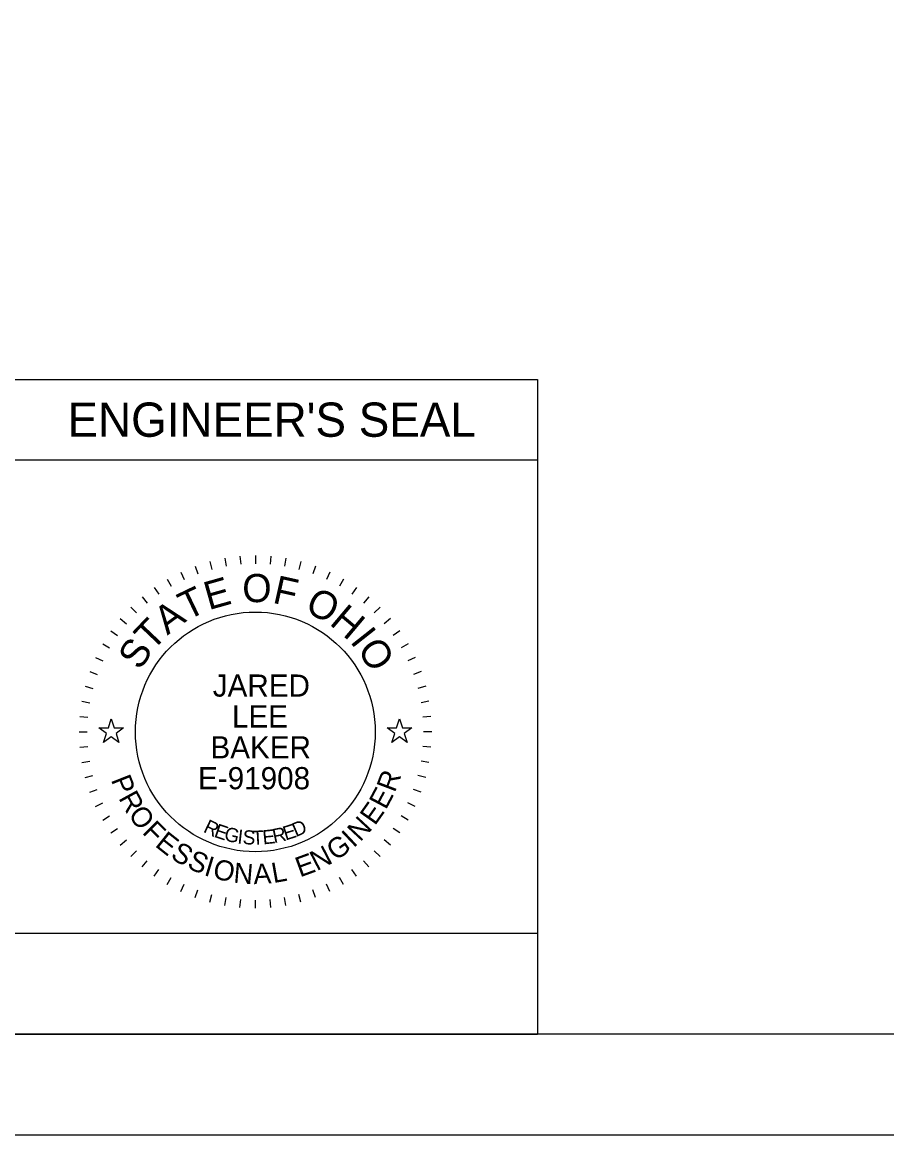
# Model space of a CAD drawing. Extents: x 0 to 70.2, y 0 to 31.4.
# Drawn here: x 21.1 to 25.39, y 0 to 5.52 of the extents above; entities that cross this region are included whole.
import ezdxf

# ---------------------------------------------------------------- set-up
doc = ezdxf.new("R2010")
doc.units = 0
for name, color, linetype in [('SH_Border', 7, 'Continuous'), ('SH_Cut_Line', 7, 'Continuous'), ('SH_Data', 7, 'Continuous'), ('SH_Seal', 7, 'Continuous')]:
    doc.layers.add(name, color=color, linetype=linetype)

msp = doc.modelspace()

# ---------------------------------------------------------------- linework, layer by layer
at = {"layer": 'SH_Border'}
msp.add_lwpolyline([(1.5, 21.5), (33.5, 21.5), (33.5, 0.5), (1.5, 0.5)], close=True, dxfattribs=at)
at = {"layer": 'SH_Cut_Line'}
msp.add_lwpolyline([(0, 0), (34, 0), (34, 22), (0, 22)], close=True, dxfattribs=at)
at = {"layer": 'SH_Data'}
for p, q in [((20.8533, 3.75), (23.6533, 3.75)), ((23.6533, 3.75), (23.6533, 0.5)), ((20.8533, 3.35), (23.6533, 3.35)), ((20.8533, 0.5), (23.6533, 0.5))]:
    msp.add_line(p, q, dxfattribs=at)
msp.add_lwpolyline([(20.8533, 0.5), (20.8533, 1), (23.6533, 1), (23.6533, 0.5)], close=True, dxfattribs=at)
at = {"layer": 'SH_Seal'}
for p, q in [((22.2533, 2.875), (22.2533, 2.835)), ((21.954, 2.8222), (21.9677, 2.7846)), ((22.0268, 2.8452), (22.0372, 2.8065)), ((22.1013, 2.8617), (22.1083, 2.8223)), ((22.177, 2.8717), (22.1805, 2.8318)), ((22.3295, 2.8717), (22.326, 2.8318)), ((22.4052, 2.8617), (22.3983, 2.8223)), ((22.4797, 2.8452), (22.4694, 2.8065)), ((22.5525, 2.8222), (22.5389, 2.7846)), ((21.8835, 2.793), (21.9004, 2.7568)), ((22.6231, 2.793), (22.6062, 2.7568)), ((21.7514, 2.7168), (21.7743, 2.684)), ((21.8158, 2.7578), (21.8358, 2.7231)), ((22.6908, 2.7578), (22.6708, 2.7231)), ((22.7552, 2.7168), (22.7322, 2.684)), ((21.6908, 2.6703), (21.7165, 2.6396)), ((22.8157, 2.6703), (22.79, 2.6396)), ((21.6346, 2.6187), (21.6628, 2.5904)), ((22.872, 2.6187), (22.8437, 2.5904)), ((21.583, 2.5624), (21.6136, 2.5367)), ((22.9236, 2.5624), (22.8929, 2.5367)), ((21.5365, 2.5019), (21.5693, 2.4789)), ((22.97, 2.5019), (22.9373, 2.4789)), ((21.4955, 2.4375), (21.5301, 2.4175)), ((23.011, 2.4375), (22.9764, 2.4175)), ((21.4603, 2.3698), (21.4965, 2.3529)), ((23.0463, 2.3698), (23.01, 2.3529)), ((21.431, 2.2993), (21.4686, 2.2856)), ((23.0755, 2.2993), (23.0379, 2.2856)), ((21.4081, 2.2265), (21.4467, 2.2161)), ((23.0985, 2.2265), (23.0598, 2.2161)), ((21.3916, 2.1519), (21.431, 2.145)), ((23.115, 2.1519), (23.0756, 2.145)), ((21.3816, 2.0763), (21.4214, 2.0728)), ((23.1249, 2.0763), (23.0851, 2.0728)), ((21.3783, 2), (21.4183, 2)), ((23.1283, 2), (23.0883, 2)), ((21.3816, 1.9237), (21.4214, 1.9272)), ((23.1249, 1.9237), (23.0851, 1.9272)), ((21.3916, 1.8481), (21.431, 1.855)), ((23.115, 1.8481), (23.0756, 1.855)), ((21.4081, 1.7735), (21.4467, 1.7839)), ((23.0985, 1.7735), (23.0598, 1.7839)), ((21.431, 1.7007), (21.4686, 1.7144)), ((23.0755, 1.7007), (23.0379, 1.7144)), ((21.4603, 1.6302), (21.4965, 1.6471)), ((23.0463, 1.6302), (23.01, 1.6471)), ((21.4955, 1.5625), (21.5301, 1.5825)), ((23.011, 1.5625), (22.9764, 1.5825)), ((21.5365, 1.4981), (21.5693, 1.5211)), ((22.97, 1.4981), (22.9373, 1.5211)), ((21.583, 1.4376), (21.6136, 1.4633)), ((22.9236, 1.4376), (22.8929, 1.4633)), ((21.6346, 1.3813), (21.6628, 1.4096)), ((22.872, 1.3813), (22.8437, 1.4096)), ((21.6908, 1.3297), (21.7165, 1.3604)), ((22.8157, 1.3297), (22.79, 1.3604)), ((21.7514, 1.2832), (21.7743, 1.316)), ((21.8158, 1.2422), (21.8358, 1.2769)), ((22.6908, 1.2422), (22.6708, 1.2769)), ((22.7552, 1.2832), (22.7322, 1.316)), ((21.8835, 1.207), (21.9004, 1.2432)), ((21.954, 1.1778), (21.9677, 1.2154)), ((22.5525, 1.1778), (22.5389, 1.2154)), ((22.6231, 1.207), (22.6062, 1.2432)), ((22.0268, 1.1548), (22.0372, 1.1935)), ((22.1013, 1.1383), (22.1083, 1.1777)), ((22.177, 1.1283), (22.1805, 1.1682)), ((22.2533, 1.125), (22.2533, 1.165)), ((22.3295, 1.1283), (22.326, 1.1682)), ((22.4052, 1.1383), (22.3983, 1.1777)), ((22.4797, 1.1548), (22.4694, 1.1935))]:
    msp.add_line(p, q, dxfattribs=at)
for points in [[(21.4769, 2.02), (21.5238, 2.02), (21.5383, 2.0645), (21.5528, 2.02), (21.5996, 2.02), (21.5618, 1.9924), (21.5763, 1.9478), (21.5383, 1.9754), (21.5003, 1.9478), (21.5148, 1.9924)], [(22.9069, 2.02), (22.9538, 2.02), (22.9683, 2.0645), (22.9828, 2.02), (23.0296, 2.02), (22.9918, 1.9924), (23.0063, 1.9478), (22.9683, 1.9754), (22.9303, 1.9478), (22.9448, 1.9924)]]:
    msp.add_lwpolyline(points, close=True, dxfattribs=at)
msp.add_circle((22.2533, 2), 0.595, dxfattribs=at)

# ---------------------------------------------------------------- texts
at = {"layer": 'SH_Data'}
msp.add_text("ENGINEER'S SEAL", height=0.17, dxfattribs=at).set_placement((21.3208, 3.465))
at = {"layer": 'SH_Seal'}
for s, height, rotation, p in [('E', 0.14, 15.7571, (22.0217, 2.6038)), ('O', 0.14, 359.7812, (22.188, 2.6443)), ('F', 0.14, 347.4362, (22.3343, 2.6417)), ('T', 0.14, 25.7167, (21.9149, 2.5518)), ('O', 0.14, 332.2586, (22.4931, 2.6015)), ('A', 0.14, 36.4747, (21.8167, 2.4781)), ('H', 0.14, 319.9136, (22.6164, 2.5361)), ('T', 0.14, 46.4344, (21.7416, 2.3964)), ('I', 0.14, 308.367, (22.7197, 2.4483)), ('S', 0.14, 57.1924, (21.6814, 2.3014)), ('O', 0.14, 303.1491, (22.7554, 2.4089)), ('P', 0.1, 291.494, (21.5355, 1.7621)), ('R', 0.1, 69.2322, (22.9452, 1.6954)), ('E', 0.1, 61.9951, (22.9009, 1.6098)), ('R', 0.1, 298.7311, (21.5722, 1.6717)), ('O', 0.1, 306.4666, (21.6187, 1.5883)), ('E', 0.1, 54.758, (22.8466, 1.5314)), ('F', 0.1, 314.7068, (21.6876, 1.4983)), ('R', 0.07, 334.487, (21.9908, 1.5051)), ('D', 0.07, 23.3052, (22.4543, 1.477)), ('N', 0.1, 47.0224, (22.7735, 1.4508)), ('E', 0.1, 321.4393, (21.7511, 1.4348)), ('E', 0.07, 341.04, (22.0439, 1.4801)), ('G', 0.07, 347.4752, (22.0947, 1.4618)), ('I', 0.07, 353.7858, (22.1623, 1.4468)), ('S', 0.07, 356.8926, (22.189, 1.4429)), ('T', 0.07, 3.0061, (22.239, 1.4387)), ('E', 0.07, 6.0117, (22.2922, 1.4412)), ('R', 0.07, 11.9184, (22.3458, 1.4474)), ('E', 0.07, 17.6836, (22.4031, 1.4602)), ('I', 0.1, 43.287, (22.7401, 1.4214)), ('S', 0.1, 328.6764, (21.8276, 1.3752)), ('G', 0.1, 35.0469, (22.6513, 1.357)), ('S', 0.1, 335.9134, (21.9097, 1.3266)), ('I', 0.1, 343.1505, (21.9939, 1.2897)), ('E', 0.1, 20.0742, (22.4745, 1.277)), ('N', 0.1, 27.3113, (22.5577, 1.3075)), ('O', 0.1, 346.8859, (22.0371, 1.2751)), ('N', 0.1, 355.1261, (22.1421, 1.2517)), ('A', 0.1, 2.8617, (22.2455, 1.2437)), ('L', 0.1, 10.0987, (22.3427, 1.249))]:
    msp.add_text(s, height=height, rotation=rotation, dxfattribs=at).set_placement(p)
for s, p in [('JARED', (22.0419, 2.1749)), ('LEE', (22.1372, 2.0216)), ('BAKER', (22.0305, 1.8684)), ('E-91908', (21.9689, 1.7151))]:
    msp.add_text(s, height=0.11, dxfattribs=at).set_placement(p)

doc.saveas('drawing.dxf')
